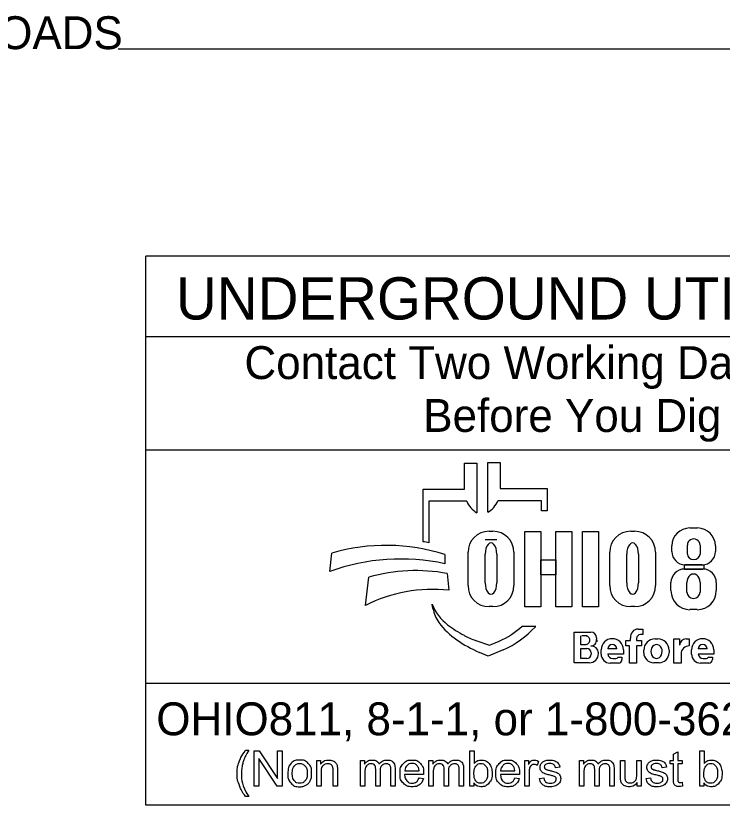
# Model space of a CAD drawing. Extents: x 0 to 34, y 0 to 22.
# Drawn here: x 2.912 to 5.919, y 7.658 to 11.019 of the extents above; entities that cross this region are included whole.
import ezdxf

# ---------------------------------------------------------------- set-up
doc = ezdxf.new("R2010")
doc.units = 0
doc.layers.add('SH_Data', color=7, linetype='Continuous')
doc.layers.add('SH_Text', color=7, linetype='Continuous')

msp = doc.modelspace()

# ---------------------------------------------------------------- linework, layer by layer
at = {"layer": 'SH_Data'}
for p, q in [((7.7, 10.8767), (3.3471, 10.8767)), ((3.4656, 7.6577), (3.4656, 9.9952)), ((7.7156, 9.9952), (3.4656, 9.9952)), ((3.4656, 9.6537), (7.7156, 9.6537)), ((3.4656, 9.1703), (7.7156, 9.1703)), ((7.7156, 8.1756), (3.4656, 8.1756)), ((7.7156, 7.6577), (3.4656, 7.6577))]:
    msp.add_line(p, q, dxfattribs=at)
at = {"layer": 'SH_Text'}
for p, q in [((4.8216, 9.0032), (4.8216, 9.1147)), ((4.8216, 9.1147), (4.8752, 9.1147)), ((4.8752, 9.1147), (4.8752, 8.9027)), ((4.9209, 8.905), (4.9209, 9.1171)), ((4.9209, 9.1171), (4.9746, 9.1171)), ((4.9746, 9.1171), (4.9746, 9.0056)), ((4.6457, 8.7793), (4.6457, 9.0032)), ((4.6457, 9.0032), (4.8216, 9.0032)), ((4.9746, 9.0056), (5.1738, 9.0056)), ((5.1738, 9.0056), (5.1738, 8.9117)), ((4.6709, 8.9518), (4.6709, 8.7749)), ((4.832, 8.9518), (4.6709, 8.9518)), ((5.1505, 8.9541), (4.9642, 8.9541)), ((5.1505, 8.9117), (5.1505, 8.9541)), ((5.1738, 8.9117), (5.1505, 8.9117)), ((4.9266, 8.8241), (4.9431, 8.8241)), ((5.5297, 8.8241), (5.5462, 8.8241)), ((5.7812, 8.8381), (5.8139, 8.8381)), ((4.9599, 8.787), (4.9101, 8.787)), ((5.7049, 8.7374), (5.7049, 8.7617)), ((5.771, 8.7261), (5.771, 8.7654)), ((5.8252, 8.7654), (5.8252, 8.7261)), ((5.8902, 8.7617), (5.8902, 8.7374)), ((4.2483, 8.653), (4.2577, 8.7312)), ((4.739, 8.7247), (4.739, 8.6859)), ((4.8371, 8.5926), (4.8371, 8.7346)), ((4.91, 8.604), (4.91, 8.7263)), ((4.9598, 8.7263), (4.9598, 8.604)), ((5.0326, 8.7346), (5.0326, 8.5926)), ((5.4402, 8.5926), (5.4402, 8.7346)), ((5.5131, 8.604), (5.5131, 8.7263)), ((5.5629, 8.7263), (5.5629, 8.604)), ((5.6357, 8.7346), (5.6357, 8.5926)), ((5.8342, 8.6814), (5.7609, 8.6814)), ((4.7489, 8.6441), (4.7552, 8.5731)), ((5.7591, 8.6631), (5.8364, 8.6631)), ((4.4001, 8.5085), (4.4148, 8.6286)), ((5.7012, 8.5712), (5.7012, 8.6053)), ((5.7687, 8.5653), (5.7687, 8.6062)), ((5.8255, 8.6062), (5.8255, 8.5653)), ((5.8943, 8.6053), (5.8943, 8.5712)), ((4.6878, 8.4956), (4.6848, 8.5135)), ((4.9431, 8.5031), (4.9266, 8.5031)), ((5.5462, 8.5031), (5.5297, 8.5031)), ((5.8133, 8.4903), (5.7821, 8.4903)), ((5.0681, 8.4197), (5.1255, 8.4197)), ((5.562, 8.4075), (5.5814, 8.4075)), ((5.5814, 8.4075), (5.5814, 8.3845)), ((5.2894, 8.264), (5.2894, 8.3947)), ((5.2894, 8.3947), (5.3606, 8.3947)), ((5.3174, 8.3412), (5.3174, 8.3782)), ((5.3426, 8.3782), (5.3213, 8.3782)), ((5.3843, 8.3709), (5.3843, 8.3631)), ((5.5287, 8.3591), (5.5287, 8.3696)), ((5.5814, 8.384), (5.5713, 8.384)), ((4.8697, 8.3594), (4.9291, 8.3389)), ((4.9291, 8.3389), (4.9701, 8.3567)), ((5.3368, 8.3412), (5.3174, 8.3412)), ((5.5094, 8.3361), (5.5094, 8.3591)), ((5.5094, 8.3591), (5.5287, 8.3591)), ((5.5243, 8.3361), (5.5094, 8.3361)), ((5.5243, 8.2628), (5.5243, 8.3361)), ((5.5548, 8.3676), (5.5548, 8.3591)), ((5.5548, 8.3591), (5.5764, 8.3591)), ((5.5764, 8.3361), (5.5548, 8.3361)), ((5.5548, 8.3361), (5.5548, 8.2628)), ((5.5764, 8.3591), (5.5764, 8.3361)), ((5.6332, 8.3657), (5.6453, 8.3657)), ((5.7134, 8.2628), (5.7134, 8.3655)), ((5.7134, 8.3655), (5.738, 8.3655)), ((5.738, 8.3655), (5.738, 8.3386)), ((5.7652, 8.3655), (5.7791, 8.3655)), ((5.7791, 8.3655), (5.7791, 8.3358)), ((4.9231, 8.2919), (4.8857, 8.3083)), ((4.9864, 8.3193), (4.9231, 8.2919)), ((5.3174, 8.2818), (5.3174, 8.3247)), ((5.3174, 8.3247), (5.3429, 8.3247)), ((5.361, 8.3066), (5.361, 8.3002)), ((5.3924, 8.3037), (5.3924, 8.3033)), ((5.4039, 8.3008), (5.4039, 8.3192)), ((5.4705, 8.3232), (5.432, 8.3232)), ((5.4985, 8.3192), (5.4985, 8.3015)), ((5.5854, 8.3071), (5.5854, 8.3179)), ((5.6931, 8.3179), (5.6931, 8.3071)), ((5.7889, 8.3008), (5.7889, 8.3192)), ((5.8554, 8.3232), (5.8169, 8.3232)), ((5.8834, 8.3192), (5.8834, 8.3015)), ((5.3426, 8.2818), (5.3174, 8.2818)), ((5.4985, 8.3015), (5.432, 8.3015)), ((5.453, 8.2823), (5.4671, 8.2823)), ((5.4757, 8.2878), (5.4925, 8.2878)), ((5.4925, 8.2878), (5.4925, 8.278)), ((5.744, 8.3009), (5.744, 8.2628)), ((5.8834, 8.3015), (5.817, 8.3015)), ((5.8379, 8.2823), (5.852, 8.2823)), ((5.8606, 8.2878), (5.8775, 8.2878)), ((5.8775, 8.2878), (5.8775, 8.278)), ((5.3531, 8.264), (5.2894, 8.264)), ((5.4773, 8.2628), (5.4419, 8.2628)), ((5.5548, 8.2628), (5.5243, 8.2628)), ((5.6504, 8.2643), (5.6282, 8.2643)), ((5.744, 8.2628), (5.7134, 8.2628)), ((5.8622, 8.2628), (5.8268, 8.2628))]:
    msp.add_line(p, q, dxfattribs=at)
for points in [[(5.079, 8.823), (5.147, 8.823), (5.147, 8.503), (5.079, 8.503)], [(5.2112, 8.823), (5.2791, 8.823), (5.2791, 8.503), (5.2112, 8.503)], [(5.3245, 8.823), (5.3933, 8.823), (5.3933, 8.503), (5.3245, 8.503)], [(5.147, 8.7031), (5.2112, 8.7031), (5.2112, 8.6391), (5.147, 8.6391)], [(5.7587, 8.6815), (5.8404, 8.6815), (5.8404, 8.663), (5.7587, 8.663)]]:
    msp.add_lwpolyline(points, close=True, dxfattribs=at)
for points in [[(3.8902, 7.8915), (3.9034, 7.8915)], [(3.9269, 7.7389), (3.9269, 7.889), (3.9473, 7.889), (4.0263, 7.7711), (4.0263, 7.889), (4.0453, 7.889), (4.0453, 7.7389), (4.0249, 7.7389), (3.9459, 7.8568), (3.9459, 7.7389), (3.9269, 7.7389)], [(4.8624, 7.7389), (4.8454, 7.7389), (4.8454, 7.889), (4.8638, 7.889), (4.8638, 7.8355)], [(5.7113, 7.7707), (5.7113, 7.8334), (5.6977, 7.8334), (5.6977, 7.8477), (5.7113, 7.8477), (5.7113, 7.8746), (5.7298, 7.8857), (5.7298, 7.8477), (5.7482, 7.8477), (5.7482, 7.8334), (5.7298, 7.8334), (5.7298, 7.7696)], [(5.8415, 7.7389), (5.8244, 7.7389), (5.8244, 7.889), (5.8428, 7.889), (5.8428, 7.8355)], [(4.1929, 7.7389), (4.1929, 7.8477), (4.2095, 7.8477), (4.2095, 7.8322)], [(4.3793, 7.7389), (4.3793, 7.8477), (4.3958, 7.8477), (4.3958, 7.8323)], [(4.6707, 7.7389), (4.6707, 7.8477), (4.6872, 7.8477), (4.6872, 7.8323)], [(5.0785, 7.7389), (5.0785, 7.8477), (5.0951, 7.8477), (5.0951, 7.8312)], [(5.1375, 7.8442), (5.1311, 7.8272)], [(5.3117, 7.7389), (5.3117, 7.8477), (5.3282, 7.8477), (5.3282, 7.8323)], [(5.486, 7.7803), (5.486, 7.8477), (5.5044, 7.8477), (5.5044, 7.7874)], [(5.5557, 7.7894), (5.5557, 7.8477), (5.5741, 7.8477), (5.5741, 7.7389), (5.5577, 7.7389)], [(4.2113, 7.7982), (4.2113, 7.7389), (4.1929, 7.7389)], [(4.2813, 7.8057), (4.2813, 7.7389), (4.2628, 7.7389), (4.2628, 7.805)], [(4.4624, 7.802), (4.4624, 7.7389), (4.444, 7.7389), (4.444, 7.8095)], [(4.5268, 7.8135), (4.5268, 7.7389), (4.5084, 7.7389), (4.5084, 7.8074)], [(4.5679, 7.8036), (4.6287, 7.8036)], [(4.7538, 7.802), (4.7538, 7.7389), (4.7354, 7.7389), (4.7354, 7.8095)], [(4.8182, 7.8135), (4.8182, 7.7389), (4.7998, 7.7389), (4.7998, 7.8074)], [(4.9759, 7.8036), (5.0367, 7.8036)], [(5.2275, 7.8195), (5.2094, 7.8171)], [(5.3948, 7.802), (5.3948, 7.7389), (5.3764, 7.7389), (5.3764, 7.8095)], [(5.4592, 7.8135), (5.4592, 7.7389), (5.4408, 7.7389), (5.4408, 7.8074)], [(5.6821, 7.8195), (5.664, 7.8171)], [(4.3977, 7.7953), (4.3977, 7.7389), (4.3793, 7.7389)], [(4.6481, 7.7885), (4.5669, 7.7885)], [(4.6285, 7.774), (4.6476, 7.7716)], [(4.6891, 7.7953), (4.6891, 7.7389), (4.6707, 7.7389)], [(5.0561, 7.7885), (4.9749, 7.7885)], [(5.0365, 7.774), (5.0555, 7.7716)], [(5.0969, 7.7958), (5.0969, 7.7389), (5.0785, 7.7389)], [(5.1411, 7.7714), (5.1593, 7.7742)], [(5.3301, 7.7953), (5.3301, 7.7389), (5.3117, 7.7389)], [(5.5956, 7.7714), (5.6138, 7.7742)], [(4.8624, 7.7525), (4.8624, 7.7389)], [(5.5577, 7.7389), (5.5577, 7.7549)], [(5.7482, 7.7553), (5.7508, 7.739)], [(5.8415, 7.7525), (5.8415, 7.7389)], [(3.9034, 7.6947), (3.8902, 7.6947)]]:
    msp.add_lwpolyline(points, dxfattribs=at)
for centre, radius, start, end in [((4.9234, 8.9886), 0.0985, 201.9296, 240.7469), ((4.8728, 8.9909), 0.0985, 299.2531, 338.0704), ((4.9266, 8.7346), 0.0895, 90, 180), ((4.9431, 8.7346), 0.0895, 0, 90), ((5.5297, 8.7346), 0.0895, 90, 180), ((5.5462, 8.7346), 0.0895, 0, 90), ((5.7812, 8.7617), 0.0763, 90, 180), ((5.8139, 8.7617), 0.0763, 0, 90), ((4.5175, 7.9704), 0.8191, 79.2074, 81.0007), ((4.4878, 7.9451), 0.8191, 72.1402, 106.3144), ((4.5508, 7.814), 0.8919, 77.8238, 109.8274), ((5.7609, 8.7374), 0.056, 180, 270), ((5.8342, 8.7374), 0.056, 270, 0), ((4.6147, 7.9243), 0.7322, 79.44, 105.8467), ((5.7591, 8.6053), 0.0579, 90, 180), ((5.8364, 8.6053), 0.0579, 0, 90), ((4.6868, 7.9411), 0.6357, 83.8248, 116.8021), ((4.9266, 8.5926), 0.0895, 180, 270), ((4.9431, 8.5926), 0.0895, 270, 0), ((5.5297, 8.5926), 0.0895, 180, 270), ((5.5462, 8.5926), 0.0895, 270, 0), ((5.7821, 8.5712), 0.081, 180, 270), ((5.8133, 8.5712), 0.081, 270, 0), ((4.8721, 8.5856), 0.2008, 201.0457, 232.5314), ((4.8291, 8.5197), 0.1433, 189.6817, 216.0884), ((4.9628, 8.6172), 0.3088, 216.0884, 235.7167), ((5.0647, 8.8369), 0.5173, 232.5314, 241.794), ((4.8267, 8.6871), 0.3602, 293.4582, 312.0712), ((4.8267, 8.6871), 0.401, 293.4582, 317.8286), ((5.562, 8.374), 0.0335, 90, 187.5187), ((4.9795, 8.678), 0.3371, 241.794, 250.9821), ((5.3386, 8.3613), 0.0169, 357.8325, 90), ((5.3606, 8.3709), 0.0238, 0, 90), ((5.5713, 8.3676), 0.0165, 90, 180), ((5.1293, 8.8614), 0.6044, 235.7167, 246.2325), ((5.3368, 8.36), 0.0187, 270, 2.0582), ((5.3602, 8.3602), 0.0243, 270, 6.6529), ((5.3603, 8.3038), 0.0321, 4.0748, 90), ((5.3708, 8.3587), 0.0175, 347.4023, 0), ((5.4512, 8.3192), 0.0473, 0, 180), ((5.4513, 8.3222), 0.0193, 2.9632, 177.0368), ((5.6332, 8.3179), 0.0478, 90, 180), ((5.6453, 8.3179), 0.0478, 0, 90), ((5.7649, 8.3386), 0.0269, 89.2449, 180), ((5.7789, 8.3009), 0.0349, 89.6033, 180), ((5.8361, 8.3192), 0.0473, 0, 180), ((5.8362, 8.3222), 0.0193, 2.9632, 177.0368), ((5.3429, 8.3066), 0.0181, 0, 90), ((5.3531, 8.3033), 0.0393, 270, 0), ((5.3594, 8.3037), 0.033, 0, 11.7502), ((5.6282, 8.3071), 0.0428, 180, 270), ((5.6504, 8.3071), 0.0428, 270, 0), ((5.3426, 8.3002), 0.0184, 270, 0), ((5.4419, 8.3008), 0.038, 180, 270), ((5.453, 8.3033), 0.021, 184.827, 270), ((5.4671, 8.2916), 0.00938, 270, 335.9979), ((5.4773, 8.278), 0.0152, 270, 0), ((5.8268, 8.3008), 0.038, 180, 270), ((5.8379, 8.3033), 0.021, 184.827, 270), ((5.852, 8.2916), 0.00938, 270, 335.9979), ((5.8622, 8.278), 0.0152, 270, 0)]:
    msp.add_arc(centre, radius, start, end, dxfattribs=at)
for centre, major_axis, ratio, start_param, end_param in [((4.9349, 8.7263), (0, 0.0484), 0.514403, 4.712389, 7.853982), ((5.538, 8.7263), (0, 0.0484), 0.514403, 4.712389, 7.853982), ((5.7981, 8.7654), (0.0271, 0), 0.969373, 0, 3.141593), ((5.7981, 8.7261), (0.0271, 0), 0.818453, 3.141593, 6.283185), ((5.7971, 8.6062), (0, 0.0358), 0.794529, 4.712389, 7.853982), ((4.9349, 8.604), (0, 0.0484), 0.514403, 1.570796, 4.712389), ((5.538, 8.604), (0, 0.0484), 0.514403, 1.570796, 4.712389), ((5.7971, 8.5653), (0.0284, 0), 0.959837, 3.141593, 6.283185), ((5.6397, 8.3125), (0, 0.029), 0.832186, 4.712389, 7.853982), ((5.6397, 8.3125), (0, 0.0302), 0.797287, 1.570796, 4.712389)]:
    msp.add_ellipse(centre, major_axis=major_axis, ratio=ratio, start_param=start_param, end_param=end_param, dxfattribs=at)
for points in [[(3.8902, 7.6947), (3.8749, 7.7139), (3.8644, 7.7397), (3.8538, 7.7656), (3.8538, 7.7932), (3.8538, 7.8176), (3.8617, 7.8399), (3.8709, 7.8658), (3.8902, 7.8915)], [(3.9034, 7.8915), (3.891, 7.8702), (3.887, 7.8611), (3.8808, 7.847), (3.8772, 7.8316), (3.8728, 7.8125), (3.8728, 7.7931), (3.8728, 7.7438), (3.9034, 7.6947)], [(4.0694, 7.7933), (4.0694, 7.8235), (4.0862, 7.838), (4.1002, 7.8501), (4.1204, 7.8501), (4.1428, 7.8501), (4.1571, 7.8354), (4.1713, 7.8207), (4.1713, 7.7948), (4.1713, 7.7738), (4.165, 7.7618), (4.1587, 7.7498), (4.1467, 7.7431), (4.1346, 7.7365), (4.1204, 7.7365), (4.0976, 7.7365), (4.0835, 7.7511), (4.0694, 7.7657), (4.0694, 7.7933)], [(4.0884, 7.7933), (4.0884, 7.7724), (4.0975, 7.762), (4.1066, 7.7516), (4.1204, 7.7516), (4.1341, 7.7516), (4.1432, 7.762), (4.1523, 7.7725), (4.1523, 7.7939), (4.1523, 7.8141), (4.1431, 7.8245), (4.134, 7.8349), (4.1204, 7.8349), (4.1066, 7.8349), (4.0975, 7.8245), (4.0884, 7.8142), (4.0884, 7.7933)], [(4.2095, 7.8322), (4.2215, 7.8501), (4.2441, 7.8501), (4.2539, 7.8501), (4.2622, 7.8466), (4.2704, 7.843), (4.2745, 7.8373), (4.2786, 7.8316), (4.2802, 7.8237), (4.2813, 7.8186), (4.2813, 7.8057)], [(4.2628, 7.805), (4.2628, 7.8163), (4.2607, 7.8218), (4.2585, 7.8274), (4.2531, 7.8308), (4.2476, 7.8341), (4.2402, 7.8341), (4.2284, 7.8341), (4.2199, 7.8266), (4.2113, 7.8191), (4.2113, 7.7982)], [(4.3958, 7.8323), (4.4009, 7.8403), (4.4094, 7.8452), (4.4179, 7.8501), (4.4288, 7.8501), (4.4409, 7.8501), (4.4486, 7.8451), (4.4564, 7.84), (4.4595, 7.831), (4.4725, 7.8501), (4.4932, 7.8501), (4.5094, 7.8501), (4.5181, 7.8411), (4.5268, 7.8322), (4.5268, 7.8135)], [(4.444, 7.8095), (4.444, 7.8218), (4.4395, 7.8279), (4.435, 7.8341), (4.4247, 7.8341), (4.4169, 7.8341), (4.4103, 7.83), (4.4037, 7.8259), (4.4007, 7.818), (4.3977, 7.8101), (4.3977, 7.7953)], [(4.5084, 7.8074), (4.5084, 7.8184), (4.5066, 7.8233), (4.5048, 7.8281), (4.5001, 7.8311), (4.4954, 7.8341), (4.489, 7.8341), (4.4776, 7.8341), (4.47, 7.8265), (4.4624, 7.8188), (4.4624, 7.802)], [(4.6476, 7.7716), (4.643, 7.7549), (4.6309, 7.7457), (4.6187, 7.7365), (4.5997, 7.7365), (4.5759, 7.7365), (4.5619, 7.7512), (4.5479, 7.7658), (4.5479, 7.7924), (4.5479, 7.8198), (4.562, 7.8349), (4.5762, 7.8501), (4.5987, 7.8501), (4.6205, 7.8501), (4.6343, 7.8352), (4.6482, 7.8204), (4.6482, 7.7934), (4.6482, 7.7918), (4.6481, 7.7885)], [(4.6287, 7.8036), (4.6275, 7.8174), (4.6217, 7.8243), (4.6129, 7.835), (4.5989, 7.835), (4.5862, 7.835), (4.5775, 7.8265), (4.5689, 7.8179), (4.5679, 7.8036)], [(4.6872, 7.8323), (4.6923, 7.8403), (4.7008, 7.8452), (4.7093, 7.8501), (4.7202, 7.8501), (4.7323, 7.8501), (4.74, 7.8451), (4.7477, 7.84), (4.7509, 7.831), (4.7638, 7.8501), (4.7846, 7.8501), (4.8008, 7.8501), (4.8095, 7.8411), (4.8182, 7.8322), (4.8182, 7.8135)], [(4.7354, 7.8095), (4.7354, 7.8218), (4.7308, 7.8279), (4.7263, 7.8341), (4.7161, 7.8341), (4.7083, 7.8341), (4.7017, 7.83), (4.6951, 7.8259), (4.6921, 7.818), (4.6891, 7.8101), (4.6891, 7.7953)], [(4.7998, 7.8074), (4.7998, 7.8184), (4.798, 7.8233), (4.7962, 7.8281), (4.7915, 7.8311), (4.7868, 7.8341), (4.7804, 7.8341), (4.7689, 7.8341), (4.7614, 7.8265), (4.7538, 7.8188), (4.7538, 7.802)], [(4.8622, 7.7941), (4.8622, 7.7745), (4.8675, 7.7658), (4.8762, 7.7516), (4.891, 7.7516), (4.9031, 7.7516), (4.9119, 7.7621), (4.9207, 7.7726), (4.9207, 7.7934), (4.9207, 7.8147), (4.9122, 7.8248), (4.9038, 7.835), (4.8918, 7.835), (4.8798, 7.835), (4.871, 7.8245), (4.8622, 7.814), (4.8622, 7.7941)], [(4.8638, 7.8355), (4.8755, 7.8501), (4.8936, 7.8501), (4.9036, 7.8501), (4.9126, 7.8461), (4.9215, 7.842), (4.9273, 7.8347), (4.9331, 7.8274), (4.9364, 7.817), (4.9397, 7.8067), (4.9397, 7.7949), (4.9397, 7.767), (4.9258, 7.7517), (4.912, 7.7365), (4.8926, 7.7365), (4.8734, 7.7365), (4.8624, 7.7525)], [(5.0555, 7.7716), (5.051, 7.7549), (5.0389, 7.7457), (5.0267, 7.7365), (5.0077, 7.7365), (4.9839, 7.7365), (4.9699, 7.7512), (4.9559, 7.7658), (4.9559, 7.7924), (4.9559, 7.8198), (4.97, 7.8349), (4.9842, 7.8501), (5.0067, 7.8501), (5.0285, 7.8501), (5.0423, 7.8352), (5.0562, 7.8204), (5.0562, 7.7934), (5.0562, 7.7918), (5.0561, 7.7885)], [(5.0367, 7.8036), (5.0355, 7.8174), (5.0297, 7.8243), (5.0209, 7.835), (5.0069, 7.835), (4.9942, 7.835), (4.9855, 7.8265), (4.9769, 7.8179), (4.9759, 7.8036)], [(5.0951, 7.8312), (5.1014, 7.8427), (5.1068, 7.8464), (5.1122, 7.8501), (5.1186, 7.8501), (5.1279, 7.8501), (5.1375, 7.8442)], [(5.2094, 7.8171), (5.2082, 7.8256), (5.2023, 7.8303), (5.1964, 7.835), (5.1856, 7.835), (5.1729, 7.835), (5.1675, 7.8308), (5.162, 7.8266), (5.162, 7.8209), (5.162, 7.8173), (5.1643, 7.8145), (5.1665, 7.8115), (5.1714, 7.8095), (5.1741, 7.8085), (5.1877, 7.8048), (5.2072, 7.7996), (5.215, 7.7963), (5.2228, 7.793), (5.2272, 7.7866), (5.2316, 7.7803), (5.2316, 7.7708), (5.2316, 7.7616), (5.2262, 7.7535), (5.2208, 7.7454), (5.2107, 7.7409), (5.2005, 7.7365), (5.1877, 7.7365), (5.1664, 7.7365), (5.1553, 7.7453), (5.1442, 7.7541), (5.1411, 7.7714)], [(5.1593, 7.7742), (5.1608, 7.7633), (5.1679, 7.7574), (5.1749, 7.7516), (5.1875, 7.7516), (5.2003, 7.7516), (5.2064, 7.7567), (5.2126, 7.7619), (5.2126, 7.7689), (5.2126, 7.7752), (5.2072, 7.7788), (5.2033, 7.7812), (5.1883, 7.785), (5.168, 7.7901), (5.1601, 7.7939), (5.1523, 7.7976), (5.1482, 7.8042), (5.1442, 7.8108), (5.1442, 7.8188), (5.1442, 7.8261), (5.1475, 7.8322), (5.1508, 7.8384), (5.1566, 7.8425), (5.1609, 7.8457), (5.1683, 7.8479), (5.1758, 7.8501), (5.1843, 7.8501), (5.1971, 7.8501), (5.2068, 7.8464), (5.2165, 7.8427), (5.2211, 7.8364), (5.2257, 7.8301), (5.2275, 7.8195)], [(5.3282, 7.8323), (5.3333, 7.8403), (5.3418, 7.8452), (5.3503, 7.8501), (5.3612, 7.8501), (5.3733, 7.8501), (5.381, 7.8451), (5.3887, 7.84), (5.3919, 7.831), (5.4048, 7.8501), (5.4256, 7.8501), (5.4418, 7.8501), (5.4505, 7.8411), (5.4592, 7.8322), (5.4592, 7.8135)], [(5.3764, 7.8095), (5.3764, 7.8218), (5.3718, 7.8279), (5.3673, 7.8341), (5.3571, 7.8341), (5.3493, 7.8341), (5.3427, 7.83), (5.3361, 7.8259), (5.3331, 7.818), (5.3301, 7.8101), (5.3301, 7.7953)], [(5.4408, 7.8074), (5.4408, 7.8184), (5.439, 7.8233), (5.4372, 7.8281), (5.4325, 7.8311), (5.4278, 7.8341), (5.4214, 7.8341), (5.4099, 7.8341), (5.4024, 7.8265), (5.3948, 7.8188), (5.3948, 7.802)], [(5.664, 7.8171), (5.6627, 7.8256), (5.6568, 7.8303), (5.6509, 7.835), (5.6402, 7.835), (5.6275, 7.835), (5.622, 7.8308), (5.6166, 7.8266), (5.6166, 7.8209), (5.6166, 7.8173), (5.6188, 7.8145), (5.6211, 7.8115), (5.6259, 7.8095), (5.6287, 7.8085), (5.6422, 7.8048), (5.6618, 7.7996), (5.6696, 7.7963), (5.6773, 7.793), (5.6818, 7.7866), (5.6862, 7.7803), (5.6862, 7.7708), (5.6862, 7.7616), (5.6808, 7.7535), (5.6754, 7.7454), (5.6652, 7.7409), (5.6551, 7.7365), (5.6422, 7.7365), (5.621, 7.7365), (5.6099, 7.7453), (5.5987, 7.7541), (5.5956, 7.7714)], [(5.6138, 7.7742), (5.6154, 7.7633), (5.6224, 7.7574), (5.6295, 7.7516), (5.6421, 7.7516), (5.6548, 7.7516), (5.661, 7.7567), (5.6672, 7.7619), (5.6672, 7.7689), (5.6672, 7.7752), (5.6617, 7.7788), (5.6579, 7.7812), (5.6428, 7.785), (5.6225, 7.7901), (5.6147, 7.7939), (5.6068, 7.7976), (5.6028, 7.8042), (5.5987, 7.8108), (5.5987, 7.8188), (5.5987, 7.8261), (5.6021, 7.8322), (5.6054, 7.8384), (5.6112, 7.8425), (5.6155, 7.8457), (5.6229, 7.8479), (5.6303, 7.8501), (5.6389, 7.8501), (5.6517, 7.8501), (5.6614, 7.8464), (5.6711, 7.8427), (5.6757, 7.8364), (5.6803, 7.8301), (5.6821, 7.8195)], [(5.8412, 7.7941), (5.8412, 7.7745), (5.8466, 7.7658), (5.8552, 7.7516), (5.8701, 7.7516), (5.8821, 7.7516), (5.8909, 7.7621), (5.8997, 7.7726), (5.8997, 7.7934), (5.8997, 7.8147), (5.8913, 7.8248), (5.8829, 7.835), (5.8709, 7.835), (5.8588, 7.835), (5.85, 7.8245), (5.8412, 7.814), (5.8412, 7.7941)], [(5.8428, 7.8355), (5.8545, 7.8501), (5.8726, 7.8501), (5.8827, 7.8501), (5.8916, 7.8461), (5.9006, 7.842), (5.9064, 7.8347), (5.9122, 7.8274), (5.9154, 7.817), (5.9187, 7.8067), (5.9187, 7.7949), (5.9187, 7.767), (5.9049, 7.7517), (5.8911, 7.7365), (5.8717, 7.7365), (5.8524, 7.7365), (5.8415, 7.7525)], [(5.1311, 7.8272), (5.1243, 7.8311), (5.1176, 7.8311), (5.1116, 7.8311), (5.1068, 7.8275), (5.102, 7.8238), (5.1, 7.8174), (5.0969, 7.8075), (5.0969, 7.7958)], [(4.5669, 7.7885), (4.5679, 7.7706), (4.5771, 7.7611), (4.5862, 7.7516), (4.5998, 7.7516), (4.61, 7.7516), (4.6171, 7.7569), (4.6243, 7.7623), (4.6285, 7.774)], [(4.9749, 7.7885), (4.9759, 7.7706), (4.985, 7.7611), (4.9942, 7.7516), (5.0078, 7.7516), (5.0179, 7.7516), (5.0251, 7.7569), (5.0323, 7.7623), (5.0365, 7.774)], [(5.5577, 7.7549), (5.545, 7.7365), (5.5232, 7.7365), (5.5135, 7.7365), (5.5052, 7.7401), (5.4969, 7.7438), (5.4928, 7.7494), (5.4888, 7.755), (5.4871, 7.7631), (5.486, 7.7685), (5.486, 7.7803)], [(5.5044, 7.7874), (5.5044, 7.7729), (5.5056, 7.7679), (5.5073, 7.7607), (5.5129, 7.7565), (5.5186, 7.7524), (5.5268, 7.7524), (5.5351, 7.7524), (5.5424, 7.7566), (5.5497, 7.7609), (5.5527, 7.7682), (5.5557, 7.7755), (5.5557, 7.7894)], [(5.7508, 7.739), (5.7431, 7.7374), (5.7369, 7.7374), (5.7269, 7.7374), (5.7214, 7.7406), (5.7158, 7.7437), (5.7136, 7.7489), (5.7113, 7.7541), (5.7113, 7.7707)], [(5.7298, 7.7696), (5.7298, 7.7617), (5.7307, 7.7595), (5.7317, 7.7572), (5.7339, 7.7559), (5.7361, 7.7545), (5.7402, 7.7545), (5.7432, 7.7545), (5.7482, 7.7553)]]:
    msp.add_open_spline(points, degree=3, dxfattribs=at)

# ---------------------------------------------------------------- texts
for s, height, p in [('OTHER ROADS', 0.14, (1.9944, 10.8767)), ('UNDERGROUND UTILITIES', 0.18, (3.5937, 9.7256)), ('Contact Two Working Days', 0.14, (3.8852, 9.4721)), ('Before You Dig', 0.14, (4.6464, 9.2471)), ('OHIO811, 8-1-1, or 1-800-362-2764', 0.14, (3.51, 7.9555))]:
    msp.add_text(s, height=height, dxfattribs=at).set_placement(p)

doc.saveas('drawing.dxf')
